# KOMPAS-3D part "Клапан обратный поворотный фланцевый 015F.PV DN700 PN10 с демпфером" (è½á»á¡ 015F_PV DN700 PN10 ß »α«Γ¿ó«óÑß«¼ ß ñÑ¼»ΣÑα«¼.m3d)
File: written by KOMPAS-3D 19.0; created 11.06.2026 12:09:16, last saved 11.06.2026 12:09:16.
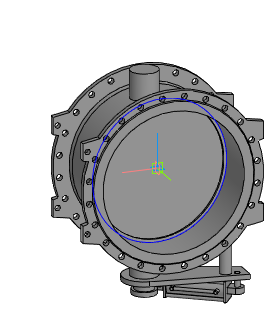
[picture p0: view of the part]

Document properties: Автор: Энергия; Полное имя файла: Z:\3.Личные\kachalov\001_3d для проектировщиков\5.5 Тип 015F.PV Клапан обратный поворотный с двумя эксцентриками\_stp_Клапан 015F.PV DN300-DN1200 с противовесом с демпфером\Клапан 015F_PV DN700 PN10 с противовесом с демпфером.m3d

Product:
- Part/product: Клапан обратный поворотный фланцевый 015F.PV DN700 PN10 с демпфером

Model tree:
1. Операция без истории:1
2. Сплайн:1
     Координата Y = 30; Координата Z = 350; Вес = 1; Координата X = 700; Координата Y = 122.157; Координата Z = 350; Вес = 0.333333; Координата X = 700; Координата Y = 122.157; Координата Z = -350; Вес = 0.333333; Координата Y = 30; Координата Z = -350; Вес = 1; Координата X = -700; Координата Y = -62.1567; Координата Z = -350; Вес = 0.333333; Координата X = -700; Координата Y = -62.1567; Координата Z = 350; Вес = 0.333333; Порядок = 4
